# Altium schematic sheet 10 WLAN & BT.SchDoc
size 297 x 209 mm
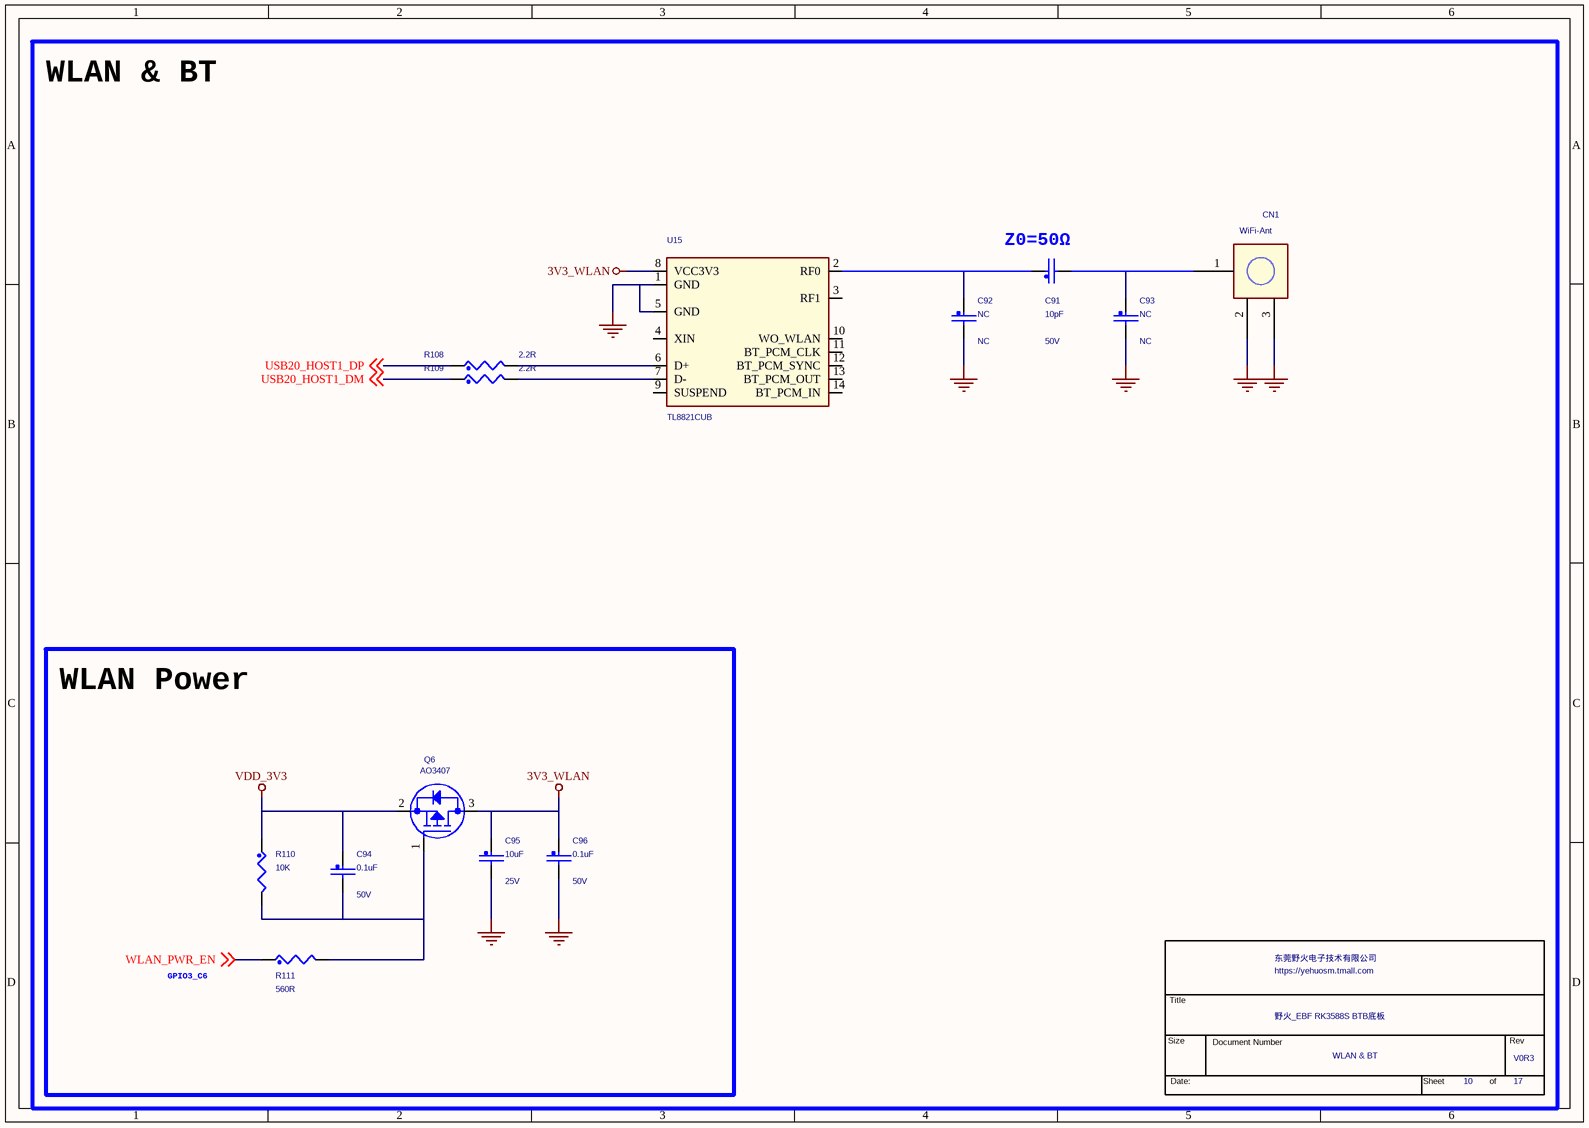
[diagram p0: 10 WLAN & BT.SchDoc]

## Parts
*  Page Count: 17  Page Number: 10  OrgName: 东莞野火电子技术有限公司  Title: 野火_EBF RK3588S BTB底板  RevCode: V0R3  Doc: WLAN & BT  (hidden comment: TitleBlock_YHSCH)  (graphical)
C91  10pF  Voltage: 50V  [C0402]
C92  NC  [C0402]
C93  NC  [C0402]
C94  0.1uF  Voltage: 50V  [C0402]
C95  10uF  Voltage: 25V  [C0603]
C96  0.1uF  Voltage: 50V  [C0402]
CN1  WiFi-Ant  [UFL-3]
Q6  AO3407  [SOT23]
R108  2.2R  [R0402]
R109  2.2R  [R0402]
R110  10K  [R0402]
R111  560R  [R0402]
U15  TL8821CUB  [RL-UM02WBS-8723BU]

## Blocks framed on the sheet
WLAN Power: C94-C96 Q6 R110 R111

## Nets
3V3_WLAN: C95.1 C96.1 Q6.3(DRAIN) U15.8(VCC3V3)
GND: C92.2 C93.2 C95.2 C96.2 CN1.2 CN1.3 U15.1(GND) U15.5(GND)
VDD_3V3: C94.1 Q6.2(SOURCE) R110.1
USB20_HOST1_DM: R109.1 ; off-sheet USB20_HOST1_DM
USB20_HOST1_DP: R108.1 ; off-sheet USB20_HOST1_DP
WLAN_PWR_EN: R111.1 ; off-sheet WLAN_PWR_EN
NetC91_1: C91.1 C92.1 U15.2(RF0)
NetC91_2: C91.2 C93.1 CN1.1
NetC94_2: C94.2 Q6.1(GATE) R110.2 R111.2
NetR108_2: R108.2 U15.6(D+)
NetR109_2: R109.2 U15.7(D-)

Not connected (* = marked no-connect by the designer): U15 3(RF1) 4(XIN) 9(SUSPEND) 10(WO_WLAN) 11(BT_PCM_CLK) 12(BT_PCM_SYNC) 13(BT_PCM_OUT) 14(BT_PCM_IN)

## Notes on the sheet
- WLAN & BT
- (near C91) Z0=50Ω
- GPIO3_C6

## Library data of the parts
* = TitleBlock_YHSCH: Cage Code: 1
C91 = CAP_NP: CLASS: DISCRETE; 规格: 贴片电容10pF 5% 50V C0G 0402; 规格编号: 0402CG100J500NT; 条码: EBF29060127; 品牌: 风华; 类别: 贴片电容0402; 规格书: 风华电容.pdf; 价格: 0.00453; 生命周期: 量产
C92 C93 = CAP_NP: CLASS: DISCRETE; 规格: 贴片电容NC 预留; 条码: EBF29060149; 类别: 贴片电容0402
C94 C96 = CAP_NP: CLASS: DISCRETE; 规格: 贴片电容0.1uF 10% 50V X5R 0402; 规格编号: 0402X104K500NT; 条码: EBF29060118; 品牌: 风华; 类别: 贴片电容0402; 规格书: 风华电容.pdf; 价格: 0.029826; 生命周期: 量产
C95 = CAP_NP: CLASS: DISCRETE; 生命周期: 量产; 价格: 0.109811; 规格书: 三星电容.pdf; 类别: 贴片电容0603; 品牌: 三星; 条码: EBF29060171; 规格编号: CL10A106MA8NRNC; 规格: 贴片电容10uF 20% 25V X5R 0603
CN1 = WIFI_ANT: 规格: RF同轴连接器（天线座）; 规格编号: KH-IPEX-K501-29; 条码: EBF430005; 品牌: 金航标; 类别: WiFi天线座; 规格书: 金航标-天线座.pdf; 价格: 0.247224; 生命周期: 量产
Q6 = MOSFET_P: CLASS: IC; 丝印: A7; 生命周期: 量产; 价格: 0.199827; 规格书: 合科泰-AO3407.pdf; 类别: P-MOS; 品牌: 合科泰; 条码: EBF29280012; 规格: P沟道MOS 导通电阻60mΩ 电流4.1A 3V可驱动
R108 = RES: CLASS: DISCRETE; 生命周期: 量产; 规格书: 厚声-无铅厚膜电阻.pdf; 类别: 贴片电阻0402; 品牌: 厚声; 条码: EBF29070280; 规格编号: 0402WGF220KTCE; 规格: 贴片电阻2.2R 1% 1/16W 0402; 价格: 0.003072
R109 = RES: CLASS: DISCRETE; 规格: 贴片电阻2.2R 1% 1/16W 0402; 规格编号: 0402WGF220KTCE; 条码: EBF29070280; 品牌: 厚声; 类别: 贴片电阻0402; 规格书: 厚声-无铅厚膜电阻.pdf; 生命周期: 量产; 价格: 0.003072
R110 = RES: CLASS: DISCRETE; 规格: 贴片电阻10K 1% 1/16W 0402; 规格编号: 0402WGF1002TCE; 条码: EBF29070046; 品牌: 厚声; 类别: 贴片电阻0402; 规格书: 厚声-无铅厚膜电阻.pdf; 价格: 0.002773; 生命周期: 量产
R111 = RES: CLASS: DISCRETE; 生命周期: 量产; 规格书: 厚声-无铅厚膜电阻.pdf; 类别: 贴片电阻0402; 品牌: 厚声; 条码: EBF29070272; 规格编号: 0402WGF5600TCE; 规格: 贴片电阻560R 1% 1/16W 0402; 价格: 0.002258
U15 = RTL8723: 规格: RTL8821 WiFi模块 接口类型：usb 工作电压：3.3V 传输速率：150M+433M 工作频率：2.4G+5.8G 无线标准：802.11AC/B/G/n 有效通信距离：100m; 条码: EBF29250002; 品牌: 创凌; 类别: WiFi模块; 价格: 17; 生命周期: 量产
